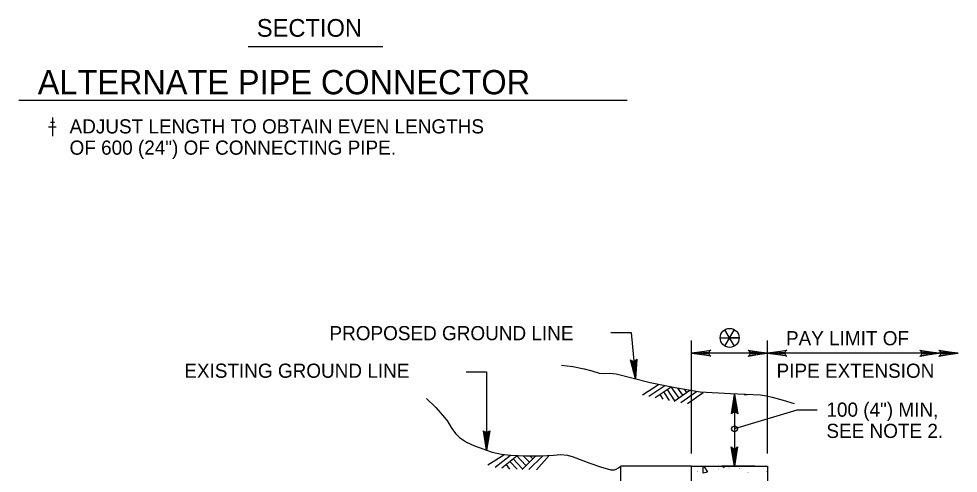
# Model space of a CAD drawing. Extents: x 637898 to 638802, y 298167 to 298761.
# Drawn here: x 638247.3 to 638470.3, y 298461.7 to 298569.5 of the extents above; entities that cross this region are included whole.
import ezdxf

# ---------------------------------------------------------------- set-up
doc = ezdxf.new("R2010")
doc.units = 0
doc.layers.add('2', color=7, linetype='Continuous')
doc.layers.add('3', color=7, linetype='Continuous')

msp = doc.modelspace()

# ---------------------------------------------------------------- linework, layer by layer
at = {"layer": '2'}
for p, q in [((638414.89, 298491.84), (638417.14, 298495.74)), ((638417.15, 298491.8), (638414.9, 298495.69)), ((638406.97, 298466.37), (638406.97, 298493.15)), ((638413.79, 298493.82), (638418.29, 298493.82)), ((638418.29, 298493.82), (638416.04, 298493.82)), ((638416.04, 298493.82), (638416.04, 298493.82)), ((638424.97, 298466.37), (638424.97, 298493.15)), ((638424.97, 298490.15), (638406.97, 298490.15)), ((638470.25, 298490.15), (638424.97, 298490.15)), ((638395.35, 298480.27), (638399.14, 298482.77)), ((638396.82, 298479.97), (638400.64, 298482.48)), ((638398.34, 298479.66), (638402.16, 298482.17)), ((638400.34, 298480.97), (638401.66, 298478.97)), ((638401.16, 298481.51), (638402.89, 298478.88)), ((638402.08, 298482.15), (638403.95, 298479.51)), ((638402.84, 298478.74), (638406.58, 298481.4)), ((638403.62, 298481.89), (638404.83, 298480.17)), ((638404.45, 298478.46), (638408.14, 298481.08)), ((638405.17, 298481.62), (638405.75, 298480.8)), ((638405.99, 298478.2), (638409.68, 298480.82)), ((638399.42, 298480.37), (638400.17, 298479.22)), ((638417.16, 298480.35), (638417.16, 298463.37)), ((638419.46, 298480.35), (638420.16, 298480.35)), ((638358.58, 298463.65), (638362.43, 298466.06)), ((638360.37, 298463.14), (638363.96, 298465.96)), ((638361.91, 298462.95), (638365.5, 298465.78)), ((638364.63, 298465.09), (638366.78, 298462.77)), ((638365.44, 298465.9), (638367.64, 298463.54)), ((638366.72, 298462.6), (638370, 298465.81)), ((638367, 298465.83), (638368.47, 298464.33)), ((638368.36, 298462.58), (638371.59, 298465.74)), ((638368.57, 298465.81), (638369.27, 298465.1)), ((638370.18, 298462.48), (638373.15, 298465.89)), ((638362.93, 298463.76), (638363.77, 298462.68)), ((638363.92, 298464.42), (638365.54, 298462.67)), ((638421.97, 298463.37), (638414.16, 298463.37))]:
    msp.add_line(p, q, dxfattribs=at)
for points in [[(638387.79, 298495.06), (638392.59, 298495.06), (638393.66, 298484.1)], [(638411.34, 298489.63), (638411.17, 298489.95), (638406.97, 298490.15), (638411.34, 298489.63), (638411.56, 298489.44), (638406.97, 298490.15), (638411.16, 298490.39), (638411.32, 298490.7), (638406.97, 298490.15), (638411.55, 298490.91), (638411.32, 298490.7)], [(638420.61, 298490.67), (638420.77, 298490.36), (638424.97, 298490.15), (638420.61, 298490.67), (638420.38, 298490.86), (638424.97, 298490.15), (638420.78, 298489.92), (638420.63, 298489.6), (638424.97, 298490.15), (638420.39, 298489.39), (638420.63, 298489.6)], [(638429.34, 298489.63), (638429.17, 298489.95), (638424.97, 298490.15), (638429.34, 298489.63), (638429.56, 298489.44), (638424.97, 298490.15), (638429.16, 298490.39), (638429.32, 298490.7), (638424.97, 298490.15), (638429.55, 298490.91), (638429.32, 298490.7)], [(638461.39, 298490.67), (638461.56, 298490.36), (638465.75, 298490.15), (638461.39, 298490.67), (638461.17, 298490.86), (638465.75, 298490.15), (638461.56, 298489.92), (638461.41, 298489.6), (638465.75, 298490.15), (638461.18, 298489.39), (638461.41, 298489.6)], [(638465.89, 298490.67), (638466.06, 298490.36), (638470.25, 298490.15), (638465.89, 298490.67), (638465.67, 298490.86), (638470.25, 298490.15), (638466.06, 298489.92), (638465.91, 298489.6), (638470.25, 298490.15), (638465.68, 298489.39), (638465.91, 298489.6)], [(638393.78, 298488.49), (638393.49, 298488.3), (638393.66, 298484.1), (638393.78, 298488.49), (638393.95, 298488.73), (638393.66, 298484.1), (638393.05, 298488.25), (638392.72, 298488.37), (638393.66, 298484.1), (638392.49, 298488.59), (638392.72, 298488.37)], [(638353.5, 298485.77), (638358.3, 298485.77), (638358.32, 298467.19)], [(638376.1, 298487.34), (638378.79, 298486.98), (638381.45, 298486.48), (638383.26, 298485.96), (638385.07, 298485.44), (638386.05, 298485.35), (638387.55, 298485.38), (638388.3, 298485.37), (638389.04, 298485.27), (638393.09, 298484.24), (638397.14, 298483.2), (638403.07, 298481.98), (638409.04, 298480.96), (638416.19, 298480.59), (638423.36, 298480.27), (638424.74, 298480.05), (638426.12, 298479.75), (638428.72, 298479.05), (638431.29, 298478.2)], [(638344.02, 298479.41), (638346.28, 298477.25), (638348.33, 298474.92), (638349, 298474), (638349.89, 298472.53), (638350.92, 298471.13), (638351.91, 298470.2), (638353.57, 298469.07), (638355.41, 298468.2), (638359.67, 298466.71), (638361.83, 298466.22), (638364.03, 298465.96), (638367.56, 298465.82), (638371.1, 298465.78), (638374.29, 298466.01), (638375.89, 298466.09), (638377.48, 298465.96), (638378.86, 298465.6), (638382.83, 298464.06), (638385.33, 298463.23), (638387.83, 298462.51), (638388.13, 298462.47), (638388.64, 298462.53), (638389.03, 298462.67), (638389.6, 298462.99), (638390.17, 298463.37)], [(638416.64, 298475.98), (638416.96, 298476.15), (638417.16, 298480.35), (638416.64, 298475.98), (638416.45, 298475.76), (638417.16, 298480.35), (638417.39, 298476.15), (638417.71, 298476), (638417.16, 298480.35), (638417.92, 298475.77), (638417.71, 298476)], [(638436.74, 298476.66), (638431.94, 298476.66), (638417.16, 298472.22)], [(638358.86, 298471.55), (638358.54, 298471.39), (638358.32, 298467.19), (638358.86, 298471.55), (638359.05, 298471.78), (638358.32, 298467.19), (638358.11, 298471.39), (638357.79, 298471.54), (638358.32, 298467.19), (638357.58, 298471.78), (638357.79, 298471.54)], [(638417.68, 298467.73), (638417.36, 298467.57), (638417.16, 298463.37), (638417.68, 298467.73), (638417.87, 298467.96), (638417.16, 298463.37), (638416.93, 298467.56), (638416.61, 298467.71), (638417.16, 298463.37), (638416.4, 298467.95), (638416.61, 298467.71)], [(638406.97, 298463.37), (638390.17, 298463.37)], [(638390.17, 298448.34), (638390.17, 298463.37)], [(638406.97, 298463.37), (638424.97, 298463.37), (638424.97, 298408.17), (638416.57, 298408.17), (638416.57, 298426.17), (638406.97, 298426.17), (638406.97, 298463.37)], [(638409.71, 298461.72), (638409.68, 298463.37)], [(638409.84, 298463.37), (638410.75, 298461.96)], [(638414.31, 298463.37), (638414.69, 298463.03)], [(638414.69, 298463.03), (638414.82, 298463.37)], [(638410.75, 298461.96), (638409.71, 298461.72)]]:
    msp.add_lwpolyline(points, dxfattribs=at)
for centre, radius in [((638416.01, 298493.79), 2.25), ((638417.16, 298472.22), 0.678)]:
    msp.add_circle(centre, radius, dxfattribs=at)
at = {"layer": '3'}
for p, q in [((638301.71, 298562.92), (638333.67, 298562.92)), ((638247.28, 298550.17), (638391.7, 298550.17)), ((638255.25, 298546.04), (638255.25, 298541.65)), ((638255.25, 298546.04), (638255.25, 298543.84)), ((638254.33, 298543.84), (638255.25, 298543.84)), ((638254.77, 298544.94), (638255.25, 298544.94)), ((638255.25, 298544.94), (638255.73, 298544.94)), ((638255.25, 298543.84), (638256.17, 298543.84))]:
    msp.add_line(p, q, dxfattribs=at)

# ---------------------------------------------------------------- texts
at = {"layer": '2'}
for p in [(638415.64, 298462.84), (638418.18, 298462.77), (638408.09, 298461.94), (638413.22, 298462.56), (638420.15, 298461.74), (638424.55, 298461.94)]:
    msp.add_text('.', height=1.12, dxfattribs=at).set_placement(p)
at = {"layer": '3'}
for s, height, p in [('SECTION', 4.2, (638303.78, 298565.2)), ('ALTERNATE PIPE CONNECTOR', 5.76, (638251.79, 298551.55)), ('ADJUST LENGTH TO OBTAIN EVEN LENGTHS', 3.36, (638259.33, 298542.27)), ('OF 600 (24") OF CONNECTING PIPE.', 3.36, (638259.33, 298537.23)), ('PROPOSED GROUND LINE', 3.36, (638321.02, 298493.23)), ('PAY LIMIT OF', 3.36, (638429.37, 298492.03)), ('EXISTING GROUND LINE', 3.36, (638286.56, 298484.32)), ('PIPE EXTENSION', 3.36, (638427.14, 298484.32)), ('100 (4") MIN,', 3.36, (638438.97, 298475.09)), ('SEE NOTE 2.', 3.36, (638438.97, 298470.05))]:
    msp.add_text(s, height=height, dxfattribs=at).set_placement(p)

doc.saveas('drawing.dxf')
